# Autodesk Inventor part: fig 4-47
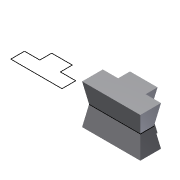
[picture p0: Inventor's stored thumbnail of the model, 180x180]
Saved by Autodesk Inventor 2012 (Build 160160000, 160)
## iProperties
Created: 2004-05
Part Number: fig 4-47
Document SubType Name: Modeling
Designer: CADCIM Technologies
Manufacturer: Standard
Standards Organization: Custom
Density: 1 g/cm^3
Material: Default
Author: CADCIM Technologies
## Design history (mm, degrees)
sketch "Sketch1"
  geometry: L1 (31.783, 34.561)-(31.783, 22.933); L2 (31.783, 22.933)-(16.796, 22.933); L3 (16.796, 22.933)-(16.796, 9.496); L4 (16.796, 9.496)-(66.925, 9.496); L5 (66.925, 9.496)-(66.925, 22.933); L6 (66.925, 22.933)-(51.938, 22.933); L7 (51.938, 22.933)-(51.938, 34.561); L8 (51.938, 34.561)-(31.783, 34.561); L9 (-45.013, 34.561)-(-45.013, 22.933); L10 (-45.013, 22.933)-(-60, 22.933); L11 (-60, 22.933)-(-60, 9.496); L12 (-60, 9.496)-(-9.871, 9.496); L13 (-9.871, 9.496)-(-9.871, 22.933); L14 (-9.871, 22.933)-(-24.858, 22.933); L15 (-24.858, 22.933)-(-24.858, 34.561); L16 (-24.858, 34.561)-(-45.013, 34.561)
  constraints: 32 end point, 10 parallel, 4 equal length, 2 collinear, 2 perpendicular, 2 vertical
extrude "Extrusion2" new body sketch "Sketch1" stored distance "d2" = 38.75; taper "d3" = 10 deg
body "Solid2"
